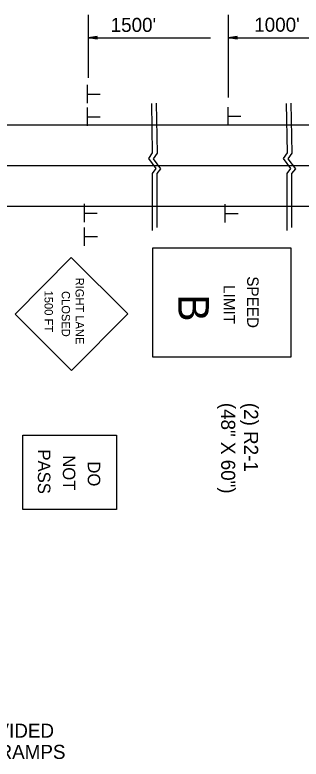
# Model space of a CAD drawing. Extents: x 1374897 to 1375063, y 381144 to 381251.
# Drawn here: x 1374958.16 to 1374970.37, y 381192.64 to 381224.39 of the extents above; entities that cross this region are included whole.
import ezdxf

# ---------------------------------------------------------------- set-up
doc = ezdxf.new("R2010")
doc.units = 0
doc.layers.add('Default', color=7, linetype='Continuous')

msp = doc.modelspace()

# ---------------------------------------------------------------- linework, layer by layer
at = {"layer": 'Default'}
for p, q in [((1374961.288, 381224.39), (1374961.288, 381221.706)), ((1374967.257, 381224.39), (1374967.257, 381220.869)), ((1374961.663, 381223.468), (1374961.288, 381223.411)), ((1374961.288, 381223.411), (1374966.507, 381223.411)), ((1374961.663, 381223.355), (1374961.288, 381223.411)), ((1374961.663, 381223.458), (1374961.35, 381223.411)), ((1374961.663, 381223.364), (1374961.35, 381223.411)), ((1374961.663, 381223.449), (1374961.415, 381223.411)), ((1374961.663, 381223.374), (1374961.415, 381223.411)), ((1374961.663, 381223.439), (1374961.477, 381223.411)), ((1374961.663, 381223.383), (1374961.477, 381223.411)), ((1374961.663, 381223.43), (1374961.541, 381223.411)), ((1374961.663, 381223.393), (1374961.541, 381223.411)), ((1374961.663, 381223.42), (1374961.603, 381223.411)), ((1374961.663, 381223.402), (1374961.603, 381223.411)), ((1374961.663, 381223.355), (1374961.663, 381223.468)), ((1374967.632, 381223.468), (1374967.257, 381223.411)), ((1374967.257, 381223.411), (1374972.476, 381223.411)), ((1374967.632, 381223.355), (1374967.257, 381223.411)), ((1374967.632, 381223.458), (1374967.32, 381223.411)), ((1374967.632, 381223.364), (1374967.32, 381223.411)), ((1374967.632, 381223.449), (1374967.384, 381223.411)), ((1374967.632, 381223.374), (1374967.384, 381223.411)), ((1374967.632, 381223.439), (1374967.446, 381223.411)), ((1374967.632, 381223.383), (1374967.446, 381223.411)), ((1374967.632, 381223.43), (1374967.51, 381223.411)), ((1374967.632, 381223.393), (1374967.51, 381223.411)), ((1374967.632, 381223.42), (1374967.573, 381223.411)), ((1374967.632, 381223.402), (1374967.573, 381223.411)), ((1374967.632, 381223.355), (1374967.632, 381223.468)), ((1374961.251, 381220.619), (1374961.251, 381221.401)), ((1374961.263, 381221.008), (1374961.797, 381221.008)), ((1374967.257, 381219.675), (1374967.257, 381220.457)), ((1374961.249, 381219.653), (1374961.249, 381220.436)), ((1374961.261, 381220.043), (1374961.795, 381220.043)), ((1374967.268, 381220.064), (1374967.802, 381220.064)), ((1374955.003, 381219.7), (1374963.663, 381219.7)), ((1374963.663, 381219.7), (1374979.655, 381219.7)), ((1374955.003, 381217.961), (1374963.663, 381217.961)), ((1374963.663, 381217.961), (1374979.655, 381217.961)), ((1374961.123, 381215.547), (1374961.123, 381216.329)), ((1374955.003, 381216.223), (1374964.581, 381216.223)), ((1374963.663, 381216.223), (1374979.655, 381216.223)), ((1374967.131, 381215.526), (1374967.131, 381216.308)), ((1374961.135, 381215.936), (1374961.669, 381215.936)), ((1374967.142, 381215.915), (1374967.676, 381215.915)), ((1374961.132, 381214.542), (1374961.132, 381215.324)), ((1374961.143, 381214.931), (1374961.677, 381214.931)), ((1374958.165, 381211.622), (1374960.566, 381214.033)), ((1374962.974, 381211.631), (1374960.566, 381214.033)), ((1374960.575, 381209.221), (1374958.165, 381211.622)), ((1374960.575, 381209.221), (1374962.974, 381211.631))]:
    msp.add_line(p, q, dxfattribs=at)
for points in [[(1374963.988, 381220.607), (1374964.02, 381218.504), (1374963.857, 381218.262), (1374964.174, 381217.829), (1374964.007, 381217.629), (1374964.007, 381215.184)], [(1374964.187, 381220.626), (1374964.22, 381218.495), (1374964.057, 381218.254), (1374964.374, 381217.821), (1374964.207, 381217.621), (1374964.207, 381215.324)], [(1374969.734, 381220.607), (1374969.766, 381218.504), (1374969.603, 381218.262), (1374969.92, 381217.829), (1374969.753, 381217.629), (1374969.753, 381215.184)], [(1374969.933, 381220.626), (1374969.966, 381218.495), (1374969.803, 381218.254), (1374970.12, 381217.821), (1374969.953, 381217.621), (1374969.953, 381215.324)]]:
    msp.add_lwpolyline(points, dxfattribs=at)
for points in [[(1374969.931, 381209.78), (1374964.044, 381209.78), (1374964.044, 381214.451), (1374969.931, 381214.451)], [(1374962.493, 381203.283), (1374958.496, 381203.283), (1374958.496, 381206.454), (1374962.493, 381206.454)]]:
    msp.add_lwpolyline(points, close=True, dxfattribs=at)

# ---------------------------------------------------------------- texts
for s, p in [("1500'", (1374962.245, 381223.664)), ("1000'", (1374968.367, 381223.672)), ('SPEED LIMIT SIGNS ARE ALSO PROVIDED', (1374943.465, 381193.549)), ('FOR PLACEMENT PAST ENTRANCE RAMPS ', (1374943.465, 381192.644))]:
    msp.add_text(s, height=0.6, dxfattribs=at).set_placement(p)
for s, height, rotation, p in [('RIGHT LANE', 0.3544, 270.1004, (1374960.745, 381213.176)), ('SPEED', 0.4865, 270, (1374968.064, 381213.236)), ('1500 FT', 0.3567, 270.0006, (1374959.424, 381212.627)), ('CLOSED', 0.3543, 270.1003, (1374960.155, 381212.604)), ('LIMIT', 0.4865, 270, (1374967.058, 381212.862)), ('B', 1.304, 270, (1374965.128, 381212.469)), ('(48" X 60")', 0.6, 270, (1374966.956, 381207.836)), ('(2) R2-1', 0.6, 270, (1374967.934, 381207.836)), ('PASS', 0.5319, 270, (1374959.141, 381205.849)), ('NOT', 0.532, 270, (1374960.205, 381205.601)), ('DO', 0.532, 270, (1374961.268, 381205.341))]:
    msp.add_text(s, height=height, rotation=rotation, dxfattribs=at).set_placement(p)

doc.saveas('drawing.dxf')
